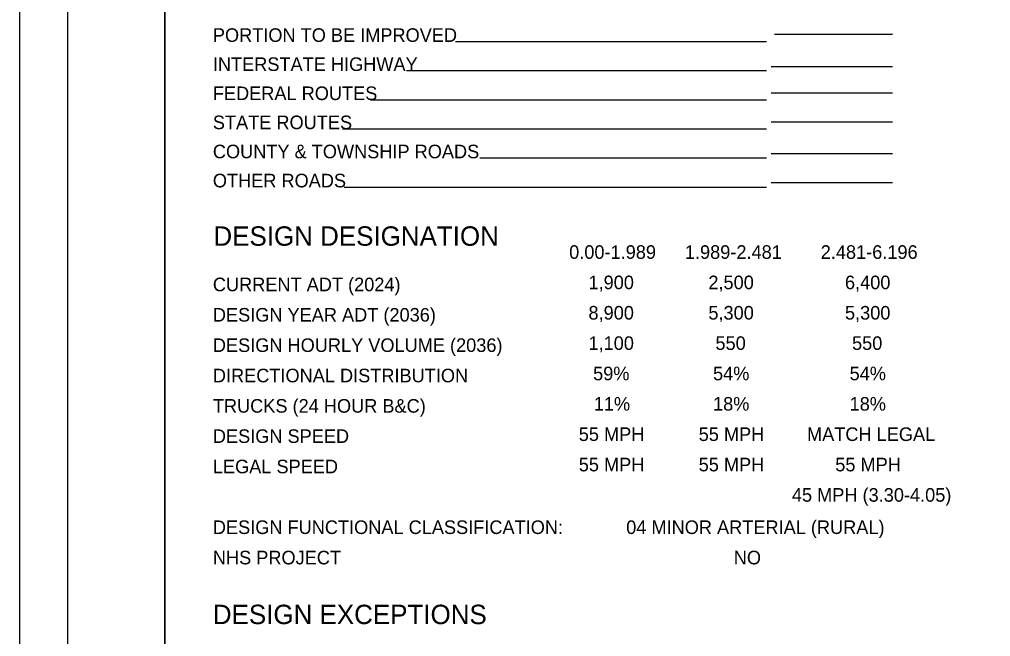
# Model space of a CAD drawing. Extents: x 0 to 36.5, y 0 to 25.3.
# Drawn here: x 0 to 10.01, y 6.25 to 12.61 of the extents above; entities that cross this region are included whole.
import ezdxf

# ---------------------------------------------------------------- set-up
doc = ezdxf.new("R2010")
doc.units = 0
for name, color, linetype in [('SH_Border', 7, 'Continuous'), ('SH_Cut_Line', 7, 'Continuous'), ('SH_Data', 7, 'Continuous'), ('SH_Text', 7, 'Continuous')]:
    doc.layers.add(name, color=color, linetype=linetype)

msp = doc.modelspace()

# ---------------------------------------------------------------- linework, layer by layer
at = {"layer": 'SH_Border'}
for points in [[(0.5, 21.5), (1.5, 21.5), (1.5, 0.5), (0.5, 0.5)], [(1.5, 21.5), (33.5, 21.5), (33.5, 0.5), (1.5, 0.5)]]:
    msp.add_lwpolyline(points, close=True, dxfattribs=at)
at = {"layer": 'SH_Cut_Line'}
msp.add_lwpolyline([(0, 0), (34, 0), (34, 22), (0, 22)], close=True, dxfattribs=at)
at = {"layer": 'SH_Data'}
for p, q in [((7.783, 12.455), (9, 12.455)), ((7.7, 12.377), (4.494, 12.377)), ((9, 12.121), (7.75, 12.121)), ((7.7, 12.077), (3.99, 12.077)), ((9, 11.849), (7.75, 11.849)), ((7.7, 11.777), (3.619, 11.777)), ((9, 11.549), (7.75, 11.549)), ((7.7, 11.477), (3.329, 11.477)), ((9, 11.222), (7.75, 11.222)), ((7.7, 11.177), (4.745, 11.177)), ((9, 10.922), (7.75, 10.922)), ((7.7, 10.877), (3.347, 10.877))]:
    msp.add_line(p, q, dxfattribs=at)

# ---------------------------------------------------------------- texts
msp.add_text('DESIGN DESIGNATION', height=0.2, dxfattribs=at).set_placement((2, 10.275))
at = {"layer": 'SH_Text'}
for s, height, p in [('PORTION TO BE IMPROVED', 0.14, (1.994, 12.377)), ('INTERSTATE HIGHWAY', 0.14, (1.994, 12.077)), ('FEDERAL ROUTES', 0.14, (1.994, 11.777)), ('STATE ROUTES', 0.14, (1.994, 11.477)), ('COUNTY & TOWNSHIP ROADS', 0.14, (1.994, 11.177)), ('OTHER ROADS', 0.14, (1.994, 10.877)), ('0.00-1.989', 0.14, (5.667, 10.14)), ('1.989-2.481', 0.14, (6.86, 10.14)), ('2.481-6.196', 0.14, (8.26, 10.14)), ('CURRENT ADT (2024)', 0.14, (1.994, 9.806)), ('1,900', 0.14, (5.866, 9.827)), ('2,500', 0.14, (7.102, 9.827)), ('6,400', 0.14, (8.51, 9.827)), ('DESIGN YEAR ADT (2036)', 0.14, (1.994, 9.493)), ('8,900', 0.14, (5.866, 9.514)), ('5,300', 0.14, (7.102, 9.514)), ('5,300', 0.14, (8.51, 9.514)), ('DESIGN HOURLY VOLUME (2036)', 0.14, (1.994, 9.18)), ('1,100', 0.14, (5.866, 9.201)), ('550', 0.14, (7.175, 9.201)), ('550', 0.14, (8.583, 9.201)), ('59%', 0.14, (5.914, 8.888)), ('54%', 0.14, (7.15, 8.888)), ('54%', 0.14, (8.558, 8.888)), ('DIRECTIONAL DISTRIBUTION', 0.14, (1.994, 8.867)), ('11%', 0.14, (5.921, 8.575)), ('18%', 0.14, (7.15, 8.575)), ('18%', 0.14, (8.558, 8.575)), ('TRUCKS (24 HOUR B&C)', 0.14, (1.994, 8.554)), ('DESIGN SPEED', 0.14, (1.994, 8.242)), ('55 MPH', 0.14, (5.766, 8.262)), ('55 MPH', 0.14, (7.002, 8.262)), ('MATCH LEGAL', 0.14, (8.119, 8.262)), ('LEGAL SPEED', 0.14, (1.994, 7.929)), ('55 MPH', 0.14, (5.766, 7.949)), ('55 MPH', 0.14, (7.002, 7.949)), ('55 MPH', 0.14, (8.41, 7.949)), ('45 MPH (3.30-4.05)', 0.14, (7.963, 7.636)), ('DESIGN FUNCTIONAL CLASSIFICATION:', 0.14, (1.994, 7.303)), ('04 MINOR ARTERIAL (RURAL)', 0.14, (6.255, 7.303)), ('NHS PROJECT', 0.14, (1.994, 6.99)), ('NO', 0.14, (7.364, 6.99)), ('DESIGN EXCEPTIONS', 0.2, (1.994, 6.374))]:
    msp.add_text(s, height=height, dxfattribs=at).set_placement(p)

doc.saveas('drawing.dxf')
